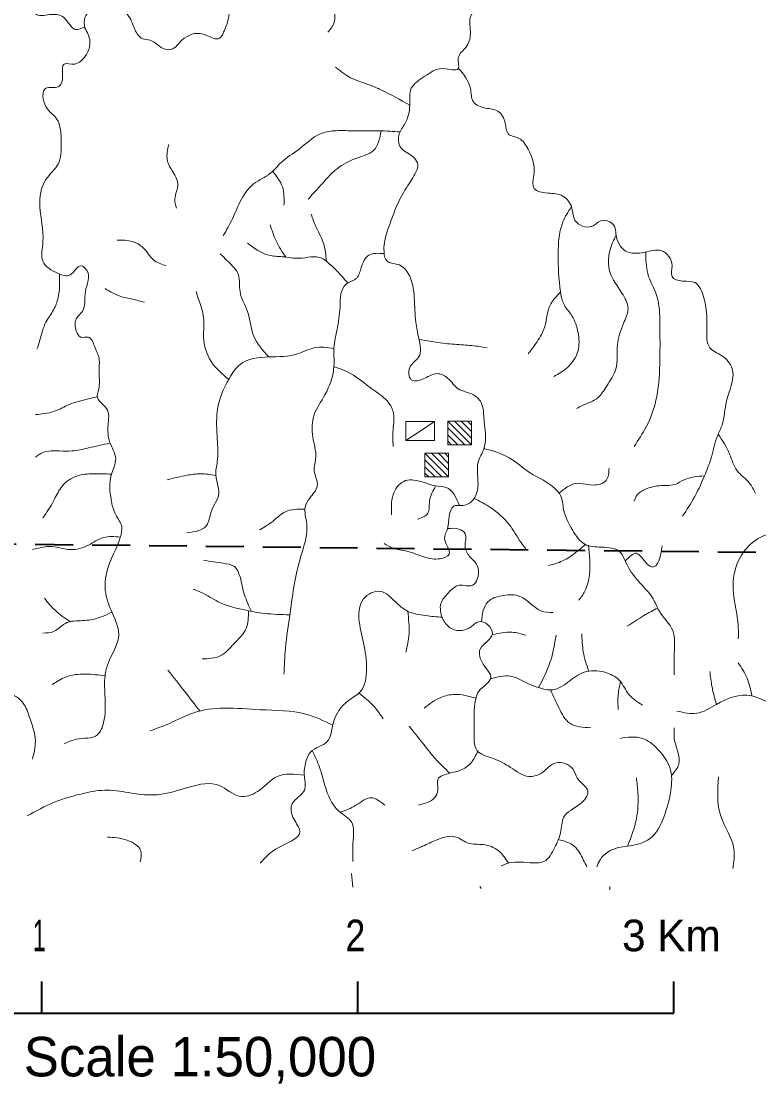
# Model space of a CAD drawing. Extents: x 789498 to 796992, y 8506099 to 8514989.
# Drawn here: x 791980 to 794313, y 8506099 to 8509460 of the extents above; entities that cross this region are included whole.
import ezdxf
from ezdxf.enums import TextEntityAlignment as Align

# ---------------------------------------------------------------- set-up
doc = ezdxf.new("R2010")
doc.units = 0
doc.header["$LTSCALE"] = 40
doc.linetypes.add('MEDIUM_DASHED', pattern=[4.5, 3, -1.5])
for name, color, linetype, lineweight in [('1', 7, 'Continuous', 13), ('15', 7, 'Continuous', 13), ('3', 7, 'Continuous', 13), ('60', 7, 'Continuous', 35), ('63', 7, 'MEDIUM_DASHED', 40)]:
    doc.layers.add(name, color=color, linetype=linetype, lineweight=lineweight)

msp = doc.modelspace()

# ---------------------------------------------------------------- linework, layer by layer
at = {"layer": '1'}
for p, q in [((793329.39, 8508194.65), (793367.39, 8508156.65)), ((793329.39, 8508173.65), (793383.39, 8508119.65)), ((793350.39, 8508194.65), (793404.39, 8508140.65)), ((793372.39, 8508194.65), (793404.39, 8508162.65)), ((793392.39, 8508194.65), (793404.39, 8508182.65)), ((793329.39, 8508151.65), (793361.39, 8508119.65)), ((793404.39, 8508119.65), (793367.39, 8508156.65)), ((793329.39, 8508131.65), (793341.39, 8508119.65)), ((793257.23, 8508093.43), (793295.23, 8508055.43)), ((793257.23, 8508072.43), (793311.23, 8508018.43)), ((793278.23, 8508093.43), (793332.23, 8508039.43)), ((793300.23, 8508093.43), (793332.23, 8508061.43)), ((793320.23, 8508093.43), (793332.23, 8508081.43)), ((793257.23, 8508050.43), (793289.23, 8508018.43)), ((793332.23, 8508018.43), (793295.23, 8508055.43)), ((793257.23, 8508030.43), (793269.23, 8508018.43))]:
    msp.add_line(p, q, dxfattribs=at)
for points in [[(793329.39, 8508194.65), (793329.39, 8508119.65), (793404.39, 8508119.65), (793404.39, 8508194.65)], [(793257.23, 8508093.43), (793257.23, 8508018.43), (793332.23, 8508018.43), (793332.23, 8508093.43)]]:
    msp.add_lwpolyline(points, close=True, dxfattribs=at)
at = {"layer": '15'}
for p, q in [((793025.16, 8506763.82), (793028.59, 8506721.2)), ((793434.68, 8506716.72), (793430.42, 8506723.11)), ((793841.86, 8506722.63), (793842.05, 8506712.23))]:
    msp.add_line(p, q, dxfattribs=at)
for points in [[(793382.88, 8509858.32), (793361.3, 8509889.51), (793322.93, 8509894.31), (793294.15, 8509875.11), (793294.15, 8509846.31), (793279.76, 8509817.51), (793231.8, 8509812.71), (793183.84, 8509798.31), (793126.29, 8509803.11), (793107.1, 8509769.51), (793059.14, 8509779.11), (793020.77, 8509764.71), (792987.2, 8509783.91), (792972.81, 8509788.71), (792958.42, 8509745.51), (792958.42, 8509711.91), (792910.46, 8509697.51), (792886.48, 8509707.11), (792862.5, 8509735.91), (792852.91, 8509769.51), (792896.07, 8509779.11), (792920.05, 8509807.91), (792905.66, 8509841.51), (792881.68, 8509841.51), (792857.7, 8509822.31), (792833.72, 8509807.91), (792790.56, 8509807.91), (792761.78, 8509783.91), (792737.8, 8509745.51), (792723.41, 8509716.71), (792713.82, 8509663.91), (792694.63, 8509620.72), (792656.27, 8509596.72), (792627.49, 8509567.92), (792637.08, 8509495.92), (792627.49, 8509443.12), (792603.51, 8509404.72), (792555.55, 8509419.12), (792488.4, 8509399.92), (792454.83, 8509371.12), (792435.64, 8509371.12), (792411.66, 8509385.52), (792387.68, 8509399.92), (792363.7, 8509404.72), (792339.72, 8509433.52), (792315.74, 8509481.52), (792272.57, 8509505.52), (792229.41, 8509505.52), (792181.45, 8509471.92), (792181.45, 8509438.32)], [(793382.88, 8509858.32), (793362.73, 8509818.94), (793367.53, 8509790.14), (793396.31, 8509766.15), (793410.69, 8509732.55), (793415.49, 8509684.55), (793449.06, 8509607.75), (793449.06, 8509545.35), (793420.29, 8509502.15), (793401.1, 8509473.35), (793401.1, 8509420.55), (793386.71, 8509377.36), (793362.73, 8509343.76), (793362.73, 8509310.16), (793314.77, 8509310.16), (793257.22, 8509286.16), (793214.05, 8509247.76), (793209.26, 8509194.96), (793194.87, 8509137.36), (793175.68, 8509103.76), (793180.48, 8509060.57), (793218.85, 8509031.77), (793233.24, 8509012.57), (793218.85, 8508964.57), (793180.48, 8508902.17), (793146.91, 8508820.57), (793127.72, 8508729.37), (793137.31, 8508700.58), (793170.89, 8508690.98), (793204.46, 8508662.18), (793223.65, 8508585.38), (793228.44, 8508508.58), (793238.03, 8508455.78), (793238.03, 8508398.18), (793209.26, 8508364.58), (793214.05, 8508326.19), (793257.22, 8508330.99), (793295.59, 8508345.39), (793329.16, 8508330.99), (793362.73, 8508297.39), (793410.69, 8508278.19), (793434.68, 8508254.19), (793444.27, 8508196.59), (793449.06, 8508153.39), (793444.27, 8508110.19), (793425.08, 8508062.19), (793425.08, 8508004.59), (793410.69, 8507947), (793372.33, 8507927.8), (793353.14, 8507927.8), (793333.96, 8507894.2), (793329.16, 8507855.8), (793319.57, 8507822.2), (793333.96, 8507774.2), (793305.18, 8507759.8), (793257.22, 8507764.6), (793199.66, 8507783.8), (793156.5, 8507793.4), (793127.72, 8507807.8)], [(792181.45, 8509443.12), (792152.67, 8509433.52), (792114.3, 8509471.92), (792075.93, 8509481.52), (792027.97, 8509481.52), (791999.19, 8509515.12), (791965.62, 8509539.12), (791932.05, 8509577.52), (791879.29, 8509572.72), (791845.72, 8509567.92), (791826.53, 8509534.32), (791807.35, 8509495.92), (791768.98, 8509491.12), (791725.82, 8509486.32), (791692.24, 8509457.52), (791687.45, 8509414.32), (791721.02, 8509351.92), (791730.61, 8509294.32), (791721.02, 8509275.13), (791663.47, 8509270.33), (791581.93, 8509294.32), (791514.79, 8509289.52), (791452.44, 8509260.73), (791423.66, 8509217.53), (791438.05, 8509179.13), (791466.82, 8509159.93), (791457.23, 8509126.33), (791394.88, 8509107.13), (791342.12, 8509073.53), (791313.35, 8509020.73), (791303.76, 8508982.33), (791265.39, 8508967.93), (791212.63, 8508967.93), (791183.85, 8508996.73), (791183.85, 8509049.53), (791193.44, 8509092.73), (791164.67, 8509164.73), (791121.5, 8509227.13), (791078.34, 8509275.13), (791059.15, 8509294.32), (791049.56, 8509327.92), (791020.78, 8509347.12), (790992.01, 8509356.72), (790943.08, 8509433.52), (790866.34, 8509495.92), (790813.58, 8509539.12), (790784.81, 8509553.52), (790746.44, 8509577.52), (790669.7, 8509567.92), (790616.94, 8509553.52), (790559.39, 8509577.52), (790444.28, 8509591.92), (790381.93, 8509577.52), (790324.38, 8509558.32), (790281.21, 8509543.92), (790170.9, 8509558.32), (790122.94, 8509591.92), (790055.79, 8509611.12), (789993.44, 8509611.12), (789950.28, 8509606.32), (789911.91, 8509563.12), (789887.93, 8509515.12), (789868.75, 8509481.52), (789830.38, 8509476.72), (789796.8, 8509491.12), (789772.82, 8509462.32), (789782.41, 8509423.92), (789796.8, 8509385.52), (789825.58, 8509390.32), (789835.17, 8509366.32), (789839.97, 8509270.33), (789796.8, 8509183.93), (789744.05, 8509126.33), (789720.07, 8509063.93), (789748.84, 8509044.73), (789763.23, 8509001.53), (789806.4, 8508977.53), (789839.97, 8508943.93), (789883.13, 8508915.14), (789897.52, 8508881.54), (789931.1, 8508867.14), (789974.26, 8508804.74), (790007.83, 8508723.14), (789988.65, 8508627.14), (789945.48, 8508526.35), (789907.11, 8508487.95), (789873.54, 8508454.35), (789825.58, 8508372.75), (789796.8, 8508305.55), (789734.45, 8508247.95), (789700.88, 8508199.96)], [(792967.76, 8509507.4), (792969.45, 8509454.15), (792950.27, 8509425.35)], [(792181.45, 8509438.32), (792197.27, 8509396.56), (792168.5, 8509334.16), (792149.31, 8509324.56), (792115.74, 8509324.56), (792110.94, 8509286.16), (792096.55, 8509252.56), (792058.18, 8509247.76), (792058.18, 8509190.16), (792091.76, 8509151.76), (792106.15, 8509074.96), (792096.55, 8509007.77), (792058.18, 8508959.77), (792039, 8508873.37), (792048.59, 8508762.97), (792048.59, 8508700.58), (792096.55, 8508662.18), (792134.92, 8508657.38), (792168.5, 8508686.18), (792187.68, 8508671.78), (792182.88, 8508604.58), (792173.29, 8508542.18), (792154.11, 8508518.18), (792154.11, 8508479.78), (792168.5, 8508460.58), (792192.48, 8508460.58), (792211.66, 8508431.78), (792226.05, 8508393.38), (792226.05, 8508350.19), (792226.05, 8508302.19), (792221.25, 8508268.59), (792250.03, 8508234.99), (792254.83, 8508182.19), (792259.62, 8508129.39), (792278.81, 8508076.59), (792264.42, 8508023.79), (792264.42, 8507947), (792278.81, 8507899), (792297.99, 8507860.6), (792293.19, 8507827), (792259.62, 8507745.4), (792245.23, 8507668.6), (792264.42, 8507596.61), (792288.4, 8507519.81), (792254.83, 8507428.61), (792245.23, 8507390.21), (792245.23, 8507318.21), (792240.44, 8507241.42), (792221.25, 8507203.02), (792154.11, 8507188.62), (792115.74, 8507174.22)], [(793209.26, 8509194.96), (793118.13, 8509242.96), (793084.56, 8509257.36), (793022.21, 8509281.36), (792974.25, 8509314.96)], [(793363.59, 8509310.89), (793401.1, 8509247.76), (793410.69, 8509204.56), (793449.06, 8509185.36), (793487.43, 8509175.76), (793511.41, 8509137.36), (793521.01, 8509103.76), (793554.58, 8509089.36), (793583.36, 8509055.77), (793602.54, 8508978.97), (793602.54, 8508930.97), (793645.7, 8508916.57), (793693.67, 8508906.97), (793722.44, 8508868.57), (793732.04, 8508830.17), (793784.79, 8508810.97), (793818.37, 8508830.17), (793856.73, 8508810.97), (793861.53, 8508786.97), (793890.31, 8508734.17), (793952.66, 8508729.37), (794005.42, 8508734.17), (794038.99, 8508686.18), (794038.99, 8508652.58), (794072.56, 8508638.18), (794110.93, 8508633.38), (794139.71, 8508585.38), (794149.3, 8508489.38), (794158.89, 8508426.98), (794202.06, 8508398.18), (794230.83, 8508354.98), (794211.65, 8508258.99), (794197.26, 8508182.19), (794182.87, 8508148.59), (794163.69, 8508081.39), (794144.5, 8508028.59), (794110.93, 8507956.6), (794072.56, 8507894.2)], [(793178.49, 8509109.69), (793113.33, 8509113.36), (793027, 8509113.36), (792969.45, 8509113.36), (792926.28, 8509103.76), (792859.14, 8509055.77), (792801.59, 8509012.57), (792768.01, 8508978.97), (792715.25, 8508945.37), (792676.89, 8508897.37), (792648.11, 8508834.97), (792619.33, 8508782.17)], [(793119.02, 8509113.17), (793094.15, 8509050.97), (793041.39, 8509026.97), (792979.04, 8508993.37), (792935.88, 8508950.17), (792887.92, 8508897.37)], [(792446.67, 8509070.16), (792441.88, 8509022.17), (792456.26, 8508988.57), (792475.45, 8508945.37), (792465.86, 8508897.37), (792470.65, 8508868.57)], [(792775.21, 8508985.9), (792806.38, 8508935.77), (792811.18, 8508878.17)], [(793720.44, 8508872.42), (793693.67, 8508825.37), (793679.28, 8508738.97), (793684.07, 8508618.98), (793698.46, 8508561.38), (793722.44, 8508527.78), (793741.63, 8508474.98), (793741.63, 8508417.38), (793708.05, 8508364.58), (793664.89, 8508335.79)], [(792945.42, 8508700.64), (792935.88, 8508758.17), (792911.9, 8508810.97), (792897.51, 8508849.37)], [(792816.77, 8508713.99), (792787.2, 8508762.97), (792768.01, 8508815.77)], [(793862.54, 8508784.2), (793842.35, 8508734.17), (793842.35, 8508666.98), (793880.72, 8508599.78), (793899.9, 8508551.78), (793885.51, 8508503.78), (793866.33, 8508436.58), (793861.53, 8508359.78), (793832.75, 8508306.99), (793803.98, 8508268.59), (793756.02, 8508244.59), (793736.83, 8508234.99)], [(792283.6, 8508767.77), (792331.56, 8508762.97), (792365.14, 8508743.77), (792398.71, 8508705.38), (792437.08, 8508686.18)], [(793011.76, 8508633.55), (792945.47, 8508700.58), (792931.08, 8508710.17), (792859.14, 8508710.17), (792806.38, 8508714.97), (792763.22, 8508719.77), (792696.07, 8508758.17)], [(792763.22, 8508398.18), (792715.25, 8508465.38), (792696.07, 8508542.18), (792672.09, 8508604.58), (792667.29, 8508657.38), (792633.72, 8508700.58), (792609.74, 8508724.57)], [(793127.54, 8508724.77), (793079.76, 8508719.77), (793055.78, 8508681.38), (793041.39, 8508647.78), (793007.82, 8508628.58), (792988.63, 8508556.58), (792979.04, 8508484.58), (792969.45, 8508426.98), (792969.45, 8508369.38), (792940.67, 8508278.19), (792907.1, 8508215.79), (792902.3, 8508143.79), (792911.9, 8508081.39), (792907.1, 8508038.19), (792916.69, 8507990.2), (792892.71, 8507951.8), (792878.32, 8507923), (792883.12, 8507870.2), (792863.93, 8507764.6), (792844.75, 8507683), (792830.36, 8507587.01), (792815.97, 8507476.61), (792811.18, 8507395.01)], [(793956.3, 8508729.52), (793962.25, 8508662.18), (793991.03, 8508590.18), (794000.62, 8508503.78), (794000.62, 8508388.58), (793991.03, 8508273.39), (793957.45, 8508177.39), (793919.08, 8508114.99)], [(792101.03, 8508660.3), (792096.55, 8508585.38), (792082.16, 8508546.98), (792058.18, 8508508.58), (792039, 8508450.98), (792029.41, 8508422.18)], [(792245.23, 8508614.18), (792293.19, 8508590.18), (792331.56, 8508580.58), (792369.93, 8508570.98)], [(792636.49, 8508327.06), (792580.96, 8508383.78), (792556.98, 8508460.58), (792556.98, 8508522.98), (792542.59, 8508575.78), (792533, 8508604.58)], [(793686.44, 8508602.79), (793655.3, 8508566.18), (793636.11, 8508494.18), (793612.13, 8508446.18), (793583.36, 8508407.78)], [(793238.32, 8508453.8), (793314.77, 8508441.38), (793372.33, 8508436.58), (793425.08, 8508431.78), (793453.86, 8508426.98)], [(792969.21, 8508425.25), (792907.1, 8508426.98), (792854.34, 8508407.78), (792763.22, 8508398.18), (792672.09, 8508374.18), (792638.52, 8508330.99), (792600.15, 8508225.39), (792600.15, 8508138.99), (792600.15, 8508066.99), (792595.35, 8508023.79), (792604.94, 8507966.2), (792580.96, 8507908.6), (792566.57, 8507865.4), (792504.22, 8507841.4)], [(792969.19, 8508367.64), (793022.21, 8508345.39), (793089.35, 8508297.39), (793137.31, 8508258.99), (793156.5, 8508225.39), (793156.5, 8508167.79), (793156.5, 8508114.99)], [(795606.72, 8507971.64), (795537.46, 8508033.67), (795509.74, 8508103), (795447.38, 8508137.67), (795378.1, 8508158.47), (795322.67, 8508241.67), (795232.6, 8508262.48), (795163.31, 8508304.08), (795121.74, 8508297.14), (795080.16, 8508255.54), (795066.31, 8508200.07), (795017.81, 8508179.27), (794969.31, 8508172.34), (794969.31, 8508116.87), (794990.09, 8508061.4), (794955.45, 8508005.93), (794872.3, 8507992.06), (794823.8, 8507985.13), (794768.37, 8507936.59), (794657.52, 8507894.99), (794567.44, 8507846.46), (794484.3, 8507853.39), (794373.44, 8507846.46), (794304.15, 8507818.72), (794241.79, 8507735.52), (794234.87, 8507638.45), (794248.72, 8507541.38), (794248.72, 8507506.71)], [(792221.34, 8508272.04), (792125.33, 8508244.59), (792082.16, 8508225.39), (792024.61, 8508215.79)], [(794184.91, 8508153.95), (794221.24, 8508090.99), (794245.22, 8508038.19), (794283.59, 8507999.8), (794302.78, 8507966.2)], [(792260.16, 8508125.63), (792192.48, 8508110.19), (792139.72, 8508100.59), (792101.35, 8508100.59), (792048.59, 8508095.79), (792024.61, 8508081.39)], [(793443.94, 8508108.71), (793523.4, 8508079.42), (793590.55, 8508031.43), (793667.28, 8507983.43), (793686.47, 8507959.43), (793696.06, 8507916.23), (793724.84, 8507849.03), (793763.21, 8507805.83), (793815.96, 8507796.23), (793873.52, 8507781.83), (793892.7, 8507748.23), (793931.07, 8507690.64), (793979.03, 8507633.04), (793998.22, 8507594.64), (794041.38, 8507532.24), (794046.18, 8507460.24), (794046.18, 8507393.04)], [(793682.43, 8507967.26), (793734.43, 8507997.83), (793796.78, 8507993.03), (793830.35, 8508007.43), (793839.94, 8508045.83)], [(792264.82, 8508026.98), (792202.07, 8508028.59), (792149.31, 8508018.99), (792106.15, 8507985.4), (792082.16, 8507942.2), (792048.59, 8507889.4)], [(792595.32, 8508023.31), (792547.39, 8508028.59), (792504.22, 8508023.79), (792441.88, 8508009.39)], [(793366.6, 8507927.83), (793324.36, 8507985.4), (793290.79, 8507990.2), (793242.83, 8508004.59), (793190.07, 8508004.59), (793156.5, 8507961.4), (793151.7, 8507899)], [(794141.85, 8508021.99), (794077.36, 8508009.39), (794048.58, 8507995), (793991.03, 8507990.2), (793957.45, 8507980.6), (793928.68, 8507961.4), (793919.08, 8507942.2)], [(793291.72, 8507989.99), (793271.61, 8507942.2), (793266.81, 8507903.8), (793233.24, 8507884.6)], [(793413.22, 8507950.67), (793465.85, 8507921.03), (793523.4, 8507868.23), (793561.77, 8507810.63), (793576.16, 8507791.43)], [(792877.02, 8507916.63), (792815.97, 8507908.6), (792777.6, 8507879.8), (792734.44, 8507851)], [(792293.68, 8507828.46), (792240.44, 8507827), (792192.48, 8507803), (792134.92, 8507788.6), (792077.37, 8507798.2), (792034.2, 8507793.4), (792015.02, 8507788.6)], [(793328.98, 8507854.91), (793365.13, 8507853.41), (793384.31, 8507839.01), (793384.31, 8507800.61), (793398.7, 8507767.01), (793422.68, 8507738.21), (793422.68, 8507695.01), (793408.29, 8507675.81), (793365.13, 8507675.81), (793331.55, 8507651.81), (793307.57, 8507618.22), (793312.37, 8507570.22)], [(793764.61, 8507805.36), (793724.84, 8507772.23), (793681.67, 8507748.23), (793648.1, 8507738.63)], [(793775.15, 8507802.58), (793777.59, 8507709.84), (793763.21, 8507657.04), (793744.02, 8507628.24)], [(793890.57, 8507751.94), (793926.27, 8507777.03), (793959.85, 8507743.43), (793979.03, 8507733.83), (794003.01, 8507772.23), (794007.81, 8507801.03)], [(792708.71, 8507592.93), (792686.48, 8507644.61), (792672.09, 8507702.2), (792652.91, 8507735.8), (792619.33, 8507745.4), (792556.98, 8507755)], [(792829.69, 8507582.3), (792748.83, 8507587.01), (792691.27, 8507596.61), (792609.74, 8507620.61), (792556.98, 8507649.4), (792523.41, 8507663.8)], [(792136.23, 8507560.4), (792086.96, 8507596.61), (792053.39, 8507635.01)], [(793311.94, 8507574.49), (793259.61, 8507579.82), (793202.06, 8507594.22), (793163.69, 8507623.02), (793115.73, 8507656.61), (793062.97, 8507632.62), (793048.58, 8507570.22), (793062.97, 8507493.42), (793072.56, 8507411.82), (793053.38, 8507339.82), (793015.01, 8507311.02), (792967.05, 8507239.03), (792947.86, 8507181.43), (792895.11, 8507147.83), (792880.72, 8507119.03), (792875.92, 8507071.03), (792875.92, 8507027.83), (792837.55, 8506984.63), (792842.35, 8506936.63), (792861.53, 8506898.24), (792784.79, 8506840.64), (792736.05, 8506796.5)], [(793435.85, 8507560.7), (793456.25, 8507623.44), (793499.42, 8507642.64), (793552.18, 8507642.64), (793590.55, 8507618.64), (793624.12, 8507594.64), (793662.49, 8507589.84)], [(792698.79, 8507595.02), (792691.27, 8507539.01), (792652.91, 8507491.01), (792609.74, 8507452.61), (792552.19, 8507443.01)], [(793993.57, 8507603.92), (793950.26, 8507580.24), (793897.5, 8507546.64)], [(792266.23, 8507590.64), (792206.86, 8507567.81), (792154.11, 8507563.01), (792125.33, 8507558.21), (792082.16, 8507529.41), (792048.59, 8507524.61)], [(793202.79, 8507593.78), (793206.85, 8507522.22), (793197.26, 8507464.62)], [(793312.37, 8507570.22), (793336.35, 8507541.42), (793398.7, 8507541.42), (793427.48, 8507560.62), (793456.25, 8507551.02), (793470.64, 8507522.22), (793432.27, 8507474.22), (793441.86, 8507426.22), (793465.85, 8507383.02), (793427.48, 8507339.82), (793417.88, 8507315.82), (793413.09, 8507215.03), (793422.68, 8507152.63), (793470.64, 8507128.63), (793528.2, 8507099.83), (793585.75, 8507071.03), (793624.12, 8507080.63), (793672.08, 8507114.23), (793724.84, 8507095.03), (793739.23, 8507066.23), (793772.8, 8507023.03), (793748.82, 8506984.63), (793696.06, 8506941.43), (793686.47, 8506893.44), (793667.28, 8506845.44), (793633.71, 8506802.24), (793600.14, 8506797.44), (793523.4, 8506797.44), (793498.33, 8506788.09)], [(793470.44, 8507519.6), (793532.99, 8507527.44), (793576.16, 8507517.84)], [(793616.97, 8507352.09), (793652.89, 8507431.44), (793667.28, 8507489.04), (793672.08, 8507517.84)], [(793774.95, 8507405.63), (793758.41, 8507465.04), (793753.61, 8507522.64)], [(794291.58, 8507326.57), (794276.44, 8507381.9), (794248.72, 8507430.44)], [(792245.12, 8507389.01), (792182.88, 8507395.01), (792120.53, 8507385.41), (792077.37, 8507361.41)], [(792544.68, 8507278.57), (792497.03, 8507339.82), (792444.27, 8507407.02)], [(793465, 8507379.4), (793528.2, 8507388.24), (793595.34, 8507359.44), (793624.12, 8507349.85), (793662.49, 8507345.05), (793715.24, 8507373.84), (793768, 8507402.64), (793835.15, 8507397.84), (793873.52, 8507373.84), (793902.29, 8507330.65), (793945.46, 8507297.05)], [(794179.43, 8507298.7), (794165.58, 8507354.17), (794158.65, 8507402.7)], [(793876.49, 8507370.52), (793868.72, 8507330.65), (793868.72, 8507282.65)], [(791694.25, 8507292.74), (791784.8, 8507322.06), (791842.36, 8507336.46), (791880.72, 8507346.06), (791938.28, 8507336.46), (791986.24, 8507302.86), (792005.42, 8507259.66), (792024.61, 8507182.86), (792015.02, 8507125.26)], [(793049.06, 8507334.43), (793096.54, 8507291.82), (793125.32, 8507253.43)], [(793418.46, 8507318.53), (793350.74, 8507330.65), (793307.57, 8507321.05), (793254.82, 8507287.45)], [(793655.92, 8507342.89), (793681.67, 8507287.45), (793715.24, 8507239.45), (793782.39, 8507225.05)], [(794538.91, 8507263.37), (794484.3, 8507326.43), (794442.73, 8507333.37), (794359.58, 8507305.63), (794290.3, 8507326.43), (794179.44, 8507298.7), (794117.08, 8507270.96), (794054.72, 8507277.9)], [(792964.59, 8507233.95), (792880.72, 8507267.83), (792736.83, 8507282.23), (792621.73, 8507287.02), (792525.8, 8507272.63), (792449.06, 8507239.03), (792386.72, 8507215.03)], [(793336.35, 8507081.05), (793288.39, 8507129.05), (793250.02, 8507177.05), (793206.85, 8507229.85)], [(794037.7, 8507074.51), (794060.57, 8507109.85), (794046.18, 8507191.45), (794046.18, 8507225.05)], [(793801.08, 8506784.75), (793811.17, 8506807.46), (793868.72, 8506845.86), (793897.5, 8506850.66), (793969.44, 8506874.66), (794012.61, 8506941.86), (794036.59, 8507037.85), (794036.59, 8507081.05), (793993.42, 8507157.85), (793945.46, 8507191.45), (793873.52, 8507191.45)], [(792900.22, 8507153.21), (792923.88, 8507099.83), (792952.66, 8507008.63), (792986.23, 8506960.63), (793024.6, 8506927.04), (793029.4, 8506859.84), (793029.4, 8506802.24)], [(793424.49, 8507151.72), (793403.5, 8507114.65), (793369.92, 8507090.65), (793336.35, 8507081.05), (793297.98, 8507061.85), (793297.98, 8507028.25), (793288.39, 8507004.25), (793235.63, 8506980.26)], [(792876.17, 8507074.86), (792789.59, 8507071.03), (792727.24, 8507023.03), (792669.69, 8507008.63), (792607.34, 8507042.23), (792511.41, 8507037.43), (792410.7, 8507013.43), (792329.16, 8507018.23), (792252.42, 8507027.83), (792180.48, 8507018.23), (792084.56, 8506989.43), (791998.23, 8506946.23)], [(793898.55, 8506850.91), (793926.27, 8506937.06), (793931.07, 8507018.65), (793926.27, 8507066.65)], [(794231.11, 8506780.01), (794234.87, 8506841.08), (794193.29, 8506945.08), (794186.37, 8507069.89)], [(792988.5, 8506958.13), (793038.99, 8506979.83), (793086.95, 8507003.83), (793130.12, 8506979.83)], [(792356.43, 8506800.69), (792357.94, 8506835.84), (792314.77, 8506869.44), (792252.42, 8506879.04)], [(793521.75, 8506797.12), (793489.83, 8506836.26), (793441.86, 8506855.46), (793393.9, 8506860.26), (793355.53, 8506879.46), (793293.18, 8506869.86), (793250.02, 8506850.66), (793216.45, 8506836.26)], [(793678.68, 8506871.76), (793729.63, 8506850.66), (793758.41, 8506807.46), (793769.92, 8506785.1)]]:
    msp.add_spline(points, degree=3, dxfattribs=at)
at = {"layer": '3'}
for p in [(793287.1, 8508193.74), (793197.1, 8508133.74)]:
    msp.add_line(p, (793242.1, 8508163.74), dxfattribs=at)
msp.add_lwpolyline([(793197.1, 8508133.74), (793287.1, 8508133.74), (793287.1, 8508193.74), (793197.1, 8508193.74)], close=True, dxfattribs=at)
at = {"layer": '60'}
for p, q in [((792045.22, 8506322.26), (792045.22, 8506422.26)), ((793045.22, 8506322.26), (793045.22, 8506422.26)), ((794045.22, 8506322.26), (794045.22, 8506422.26)), ((791045.22, 8506322.26), (794045.22, 8506322.26))]:
    msp.add_line(p, q, dxfattribs=at)
at = {"layer": '63'}
msp.add_lwpolyline([(795985.61, 8513296.58), (795924.11, 8507761.4), (790507.28, 8507821.14), (790567.65, 8513356.12), (795985.61, 8513296.58)], close=True, dxfattribs=at)

# ---------------------------------------------------------------- texts
at = {"layer": '60'}
for s, width, p in [('1', 0.55, (792037.07, 8506518.1)), ('2', 0.85, (793037.07, 8506518.1))]:
    msp.add_text(s, height=100, dxfattribs=dict(at, width=width)).set_placement(p, align=Align.CENTER)
for s, height, p in [('3 Km', 100, (794037.07, 8506518.1)), ('Scale 1:50,000', 125, (792545.22, 8506122.26))]:
    msp.add_text(s, height=height, dxfattribs=at).set_placement(p, align=Align.CENTER)

doc.saveas('drawing.dxf')
